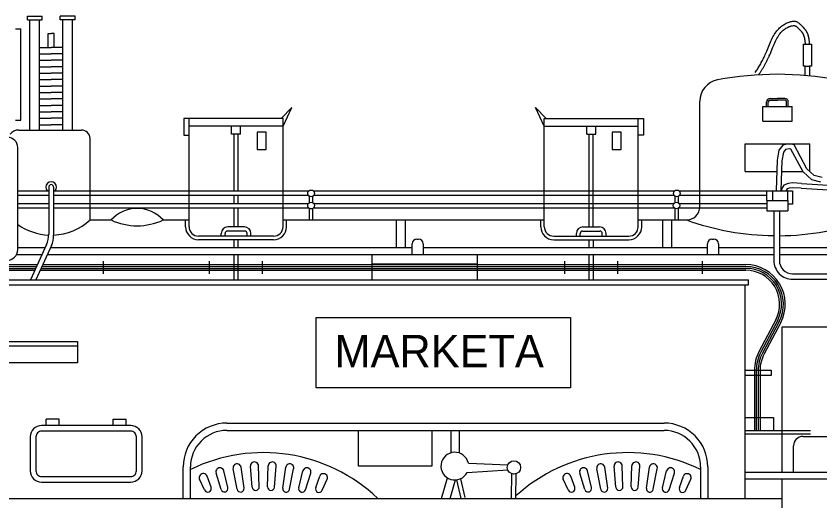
# Model space of a CAD drawing. Extents: x 2 to 10148, y 0 to 380.
# Drawn here: x 83.28 to 130.44, y 231.85 to 260.31 of the extents above; entities that cross this region are included whole.
import ezdxf

# ---------------------------------------------------------------- set-up
doc = ezdxf.new("R2010")
doc.units = 0

msp = doc.modelspace()

# ---------------------------------------------------------------- linework, layer by layer
for p, q in [((83.943, 260.309), (84.812, 260.309)), ((83.943, 260.081), (83.943, 260.309)), ((83.943, 260.081), (84.812, 260.081)), ((84.097, 253.621), (84.097, 260.081)), ((84.657, 253.621), (84.657, 260.081)), ((84.812, 260.081), (84.812, 260.309)), ((85.871, 260.081), (85.871, 260.309)), ((86.74, 260.309), (85.871, 260.309)), ((86.74, 260.081), (85.871, 260.081)), ((86.025, 253.621), (86.025, 260.081)), ((86.586, 253.621), (86.586, 260.081)), ((86.74, 260.081), (86.74, 260.309)), ((83.252, 259.551), (83.565, 259.551)), ((83.565, 254.191), (83.565, 259.551)), ((85.169, 258.469), (85.169, 259.279)), ((85.169, 259.279), (85.346, 259.279)), ((85.514, 259.279), (85.337, 259.279)), ((85.514, 258.469), (85.514, 259.279)), ((84.657, 258.469), (85.341, 258.469)), ((86.025, 258.469), (85.341, 258.469)), ((84.657, 258.091), (85.341, 258.091)), ((86.025, 258.091), (85.341, 258.091)), ((84.657, 257.713), (85.341, 257.713)), ((86.025, 257.713), (85.341, 257.713)), ((84.657, 257.335), (85.341, 257.335)), ((86.025, 257.335), (85.341, 257.335)), ((84.657, 256.957), (85.341, 256.957)), ((84.657, 256.579), (85.341, 256.579)), ((86.025, 256.957), (85.341, 256.957)), ((86.025, 256.579), (85.341, 256.579)), ((84.657, 256.201), (85.341, 256.201)), ((86.025, 256.201), (85.341, 256.201)), ((84.657, 255.824), (85.341, 255.824)), ((86.025, 255.824), (85.341, 255.824)), ((84.657, 255.446), (85.341, 255.446)), ((86.025, 255.446), (85.341, 255.446)), ((123.389, 249.124), (123.389, 255.308)), ((127.311, 255.002), (127.311, 255.266)), ((127.412, 255.002), (127.412, 255.282)), ((127.499, 255.369), (127.949, 255.369)), ((127.516, 255.47), (127.949, 255.47)), ((128.383, 255.47), (127.949, 255.47)), ((128.4, 255.369), (127.949, 255.369)), ((128.487, 255.002), (128.487, 255.282)), ((128.587, 255.002), (128.587, 255.266)), ((84.657, 255.068), (85.341, 255.068)), ((84.657, 254.69), (85.341, 254.69)), ((86.025, 255.068), (85.341, 255.068)), ((86.025, 254.69), (85.341, 254.69)), ((99.455, 254.94), (98.829, 254.295)), ((98.943, 253.85), (99.455, 254.94)), ((114.269, 253.85), (113.758, 254.94)), ((113.758, 254.94), (114.383, 254.295)), ((127.094, 254.147), (127.094, 255.002)), ((127.094, 255.002), (128.804, 255.002)), ((128.804, 254.147), (128.804, 255.002)), ((83.252, 254.191), (83.565, 254.191)), ((84.657, 254.312), (85.341, 254.312)), ((86.025, 254.312), (85.341, 254.312)), ((93.131, 254.297), (93.131, 253.327)), ((93.433, 254.295), (93.131, 254.297)), ((98.943, 254.295), (93.433, 254.295)), ((93.433, 247.943), (93.433, 254.295)), ((98.943, 247.943), (98.943, 254.295)), ((114.269, 247.943), (114.269, 254.295)), ((114.269, 254.295), (119.779, 254.295)), ((119.779, 254.295), (120.081, 254.297)), ((119.779, 247.943), (119.779, 254.295)), ((120.081, 254.297), (120.081, 253.327)), ((84.657, 253.934), (85.341, 253.934)), ((86.025, 253.934), (85.341, 253.934)), ((98.943, 253.85), (93.433, 253.85)), ((95.925, 253.375), (95.925, 253.85)), ((96.452, 253.375), (96.452, 253.85)), ((114.269, 253.85), (119.779, 253.85)), ((116.761, 253.375), (116.761, 253.85)), ((117.288, 253.375), (117.288, 253.85)), ((127.094, 254.147), (128.804, 254.147)), ((127.094, 254.147), (128.804, 254.147)), ((83.435, 253.621), (87.125, 253.621)), ((93.131, 253.327), (93.427, 253.327)), ((96.452, 253.375), (95.925, 253.375)), ((96.069, 250.05), (96.069, 253.375)), ((96.307, 250.05), (96.307, 253.375)), ((97.952, 253.487), (97.425, 253.487)), ((97.425, 253.487), (97.425, 252.477)), ((97.952, 252.477), (97.952, 253.487)), ((116.761, 253.375), (117.288, 253.375)), ((116.905, 247.938), (116.905, 253.375)), ((117.144, 247.938), (117.144, 253.375)), ((118.262, 253.487), (118.262, 252.477)), ((118.789, 253.487), (118.262, 253.487)), ((118.789, 252.477), (118.789, 253.487)), ((120.081, 253.327), (119.785, 253.327)), ((87.622, 248.34), (87.622, 253.124)), ((126.049, 252.805), (129.849, 252.805)), ((126.049, 251.19), (126.049, 252.805)), ((129.849, 251.19), (129.849, 252.805)), ((83.379, 246.6), (83.379, 252.597)), ((97.425, 252.477), (97.952, 252.477)), ((118.262, 252.477), (118.789, 252.477)), ((126.049, 251.19), (127.907, 251.19)), ((128.189, 251.19), (129.439, 251.19)), ((129.84, 251.19), (129.849, 251.19)), ((129.361, 250.486), (147.884, 249.35)), ((83.379, 250.05), (85.197, 250.05)), ((85.197, 250.271), (85.197, 247.504)), ((85.486, 250.271), (85.486, 247.444)), ((85.486, 250.05), (100.46, 250.05)), ((100.714, 250.05), (121.913, 250.05)), ((122.168, 250.05), (127.661, 250.05)), ((127.332, 249.478), (127.332, 250.056)), ((127.332, 250.056), (127.661, 250.056)), ((127.661, 250.056), (127.661, 249.481)), ((127.661, 250.056), (128.567, 250.056)), ((128.567, 249.478), (128.567, 250.056)), ((128.567, 250.056), (128.828, 250.056)), ((128.828, 250.056), (128.828, 249.271)), ((129.344, 250.205), (147.867, 249.069)), ((83.379, 249.799), (85.197, 249.799)), ((85.486, 249.799), (100.423, 249.799)), ((96.069, 249.301), (96.069, 249.799)), ((96.307, 249.301), (96.307, 249.799)), ((100.488, 249.351), (100.488, 249.735)), ((100.69, 249.349), (100.69, 249.738)), ((100.751, 249.799), (121.876, 249.799)), ((121.942, 249.351), (121.942, 249.735)), ((122.143, 249.349), (122.143, 249.738)), ((122.205, 249.799), (127.332, 249.799)), ((127.332, 249.478), (127.332, 248.872)), ((127.332, 249.478), (128.567, 249.478)), ((128.567, 249.478), (128.567, 248.872)), ((83.379, 249.301), (85.197, 249.301)), ((83.379, 249.05), (85.197, 249.05)), ((85.486, 249.301), (100.432, 249.301)), ((85.486, 249.05), (100.446, 249.05)), ((96.069, 247.938), (96.069, 249.05)), ((96.307, 247.938), (96.307, 249.05)), ((100.488, 248.34), (100.488, 249.016)), ((100.69, 248.34), (100.69, 249.019)), ((100.728, 249.05), (121.9, 249.05)), ((100.742, 249.301), (121.864, 249.301)), ((121.942, 248.34), (121.942, 249.016)), ((122.143, 248.34), (122.143, 249.019)), ((122.156, 249.05), (127.332, 249.05)), ((122.192, 249.301), (127.332, 249.301)), ((128.828, 249.271), (128.57, 249.271)), ((127.332, 248.872), (128.567, 248.872)), ((127.735, 248.872), (127.735, 245.966)), ((128.063, 248.872), (128.063, 245.966)), ((87.622, 248.34), (88.858, 248.34)), ((91.91, 248.34), (93.433, 248.34)), ((93.226, 247.943), (93.226, 248.34)), ((98.943, 248.34), (114.269, 248.34)), ((99.15, 247.943), (99.15, 248.34)), ((105.593, 246.725), (105.593, 248.34)), ((106.124, 246.725), (106.124, 248.34)), ((114.063, 247.943), (114.063, 248.34)), ((119.779, 248.34), (122.606, 248.34)), ((119.986, 247.943), (119.986, 248.34)), ((121.217, 246.725), (121.217, 248.34)), ((121.748, 246.725), (121.748, 248.34)), ((96.691, 247.692), (95.685, 247.692)), ((96.676, 247.938), (95.701, 247.938)), ((116.521, 247.692), (117.528, 247.692)), ((116.537, 247.938), (117.512, 247.938)), ((98.39, 247.39), (93.986, 247.39)), ((98.39, 247.183), (93.986, 247.183)), ((95.315, 247.39), (95.315, 247.553)), ((95.542, 247.39), (95.542, 247.549)), ((96.069, 246.725), (96.069, 247.183)), ((96.307, 246.725), (96.307, 247.183)), ((96.834, 247.39), (96.834, 247.549)), ((97.061, 247.39), (97.061, 247.553)), ((106.791, 247.218), (106.899, 247.218)), ((114.822, 247.39), (119.226, 247.39)), ((114.822, 247.183), (119.226, 247.183)), ((116.152, 247.39), (116.152, 247.553)), ((116.378, 247.39), (116.378, 247.549)), ((116.909, 246.725), (116.909, 247.183)), ((117.148, 246.725), (117.148, 247.183)), ((117.671, 247.39), (117.671, 247.549)), ((117.897, 247.39), (117.897, 247.553)), ((124.108, 247.218), (124.215, 247.218)), ((83.379, 246.725), (84.988, 246.725)), ((85.067, 246.899), (84.131, 244.825)), ((85.356, 246.839), (84.447, 244.825)), ((85.304, 246.725), (106.52, 246.725)), ((106.52, 246.315), (106.52, 246.947)), ((107.17, 246.947), (107.17, 246.323)), ((107.17, 246.725), (123.836, 246.725)), ((123.836, 246.315), (123.836, 246.947)), ((124.487, 246.947), (124.487, 246.323)), ((124.487, 246.725), (127.735, 246.725)), ((128.063, 246.725), (149.521, 246.725)), ((83.311, 246.315), (84.803, 246.315)), ((85.119, 246.315), (127.735, 246.315)), ((96.069, 244.825), (96.069, 246.315)), ((96.307, 244.825), (96.307, 246.315)), ((104.168, 244.825), (104.168, 246.315)), ((110.343, 244.825), (110.343, 246.315)), ((116.909, 244.825), (116.909, 246.315)), ((117.148, 244.825), (117.148, 246.315)), ((128.063, 246.315), (151.309, 246.315)), ((82.112, 245.722), (84.536, 245.722)), ((84.852, 245.722), (126.088, 245.722)), ((88.406, 245.189), (88.406, 245.923)), ((94.631, 245.189), (94.631, 245.923)), ((97.745, 245.189), (97.745, 245.923)), ((104.168, 245.766), (110.343, 245.766)), ((115.472, 245.189), (115.472, 245.923)), ((118.586, 245.189), (118.586, 245.923)), ((123.548, 245.189), (123.548, 245.923)), ((125.641, 245.722), (126.088, 245.722)), ((82.112, 245.612), (84.486, 245.612)), ((82.112, 245.501), (84.436, 245.501)), ((82.112, 245.39), (84.386, 245.39)), ((84.702, 245.39), (126.088, 245.39)), ((84.752, 245.501), (126.088, 245.501)), ((84.802, 245.612), (126.088, 245.612)), ((125.641, 245.612), (126.088, 245.612)), ((125.641, 245.501), (126.088, 245.501)), ((125.641, 245.39), (126.088, 245.39)), ((82.112, 244.825), (126.241, 244.825)), ((126.241, 244.54), (126.241, 244.825)), ((128.841, 245.189), (137.963, 245.189)), ((128.841, 244.86), (137.963, 244.86)), ((62.352, 244.54), (126.241, 244.54)), ((126.049, 232), (126.049, 244.54)), ((100.892, 238.49), (100.892, 242.618)), ((100.892, 242.618), (115.816, 242.618)), ((115.816, 242.618), (115.816, 238.49)), ((127.847, 242.476), (126.878, 240.635)), ((127.945, 242.424), (126.976, 240.584)), ((128.043, 242.373), (127.074, 240.532)), ((128.141, 242.321), (127.172, 240.481)), ((128.234, 242.07), (139.894, 242.07)), ((128.234, 233.538), (128.234, 242.07)), ((82.88, 241.215), (86.894, 241.215)), ((86.894, 241.215), (86.894, 239.958)), ((82.88, 240.944), (86.894, 240.944)), ((86.894, 239.958), (82.88, 239.958)), ((126.049, 239.527), (127.581, 239.527)), ((127.581, 239.214), (126.082, 239.214)), ((126.597, 239.497), (126.597, 235.97)), ((126.707, 239.497), (126.707, 235.97)), ((126.818, 239.497), (126.818, 235.97)), ((126.928, 239.497), (126.928, 235.97)), ((127.581, 239.527), (127.581, 239.214)), ((115.816, 238.49), (100.892, 238.49)), ((126.049, 236.753), (127.711, 236.753)), ((127.711, 236.753), (127.711, 235.97)), ((90.006, 236.275), (84.778, 236.275)), ((85.048, 236.275), (85.048, 236.645)), ((85.804, 236.645), (85.048, 236.645)), ((85.804, 236.275), (85.804, 236.645)), ((88.98, 236.645), (89.736, 236.645)), ((88.98, 236.275), (88.98, 236.645)), ((89.736, 236.275), (89.736, 236.645)), ((95.649, 236.417), (121.3, 236.417)), ((90.006, 235.943), (84.778, 235.943)), ((95.649, 235.99), (121.3, 235.99)), ((103.363, 233.892), (103.363, 235.993)), ((107.677, 235.993), (107.677, 233.892)), ((108.803, 234.694), (108.803, 235.993)), ((109.303, 234.694), (109.303, 235.993)), ((129.897, 235.97), (126.049, 235.97)), ((84.115, 235.611), (84.115, 233.614)), ((84.446, 235.611), (84.446, 233.614)), ((90.338, 233.614), (90.338, 235.611)), ((90.67, 233.614), (90.67, 235.611)), ((129.897, 235.759), (126.049, 235.759)), ((129.446, 235.637), (134.516, 235.637)), ((128.894, 233.538), (128.894, 235.084)), ((97.547, 232.683), (97.51, 233.911)), ((98.033, 232.682), (98.07, 233.911)), ((109.816, 234.072), (112.125, 233.961)), ((118.882, 232.683), (118.845, 233.911)), ((119.367, 232.682), (119.405, 233.911)), ((93.085, 232), (93.085, 233.853)), ((93.512, 232), (93.512, 233.853)), ((95.306, 232.522), (95.013, 233.488)), ((95.701, 232.635), (95.468, 233.619)), ((96.251, 232.537), (96.014, 233.743)), ((96.655, 232.606), (96.481, 233.823)), ((97.138, 232.66), (97.038, 233.885)), ((98.442, 232.659), (98.543, 233.885)), ((98.925, 232.605), (99.1, 233.822)), ((99.329, 232.536), (99.566, 233.742)), ((99.865, 232.62), (100.112, 233.617)), ((100.259, 232.506), (100.567, 233.486)), ((107.677, 233.892), (103.363, 233.892)), ((109.748, 233.523), (112.124, 233.676)), ((112.353, 232), (112.367, 233.473)), ((112.603, 232), (112.617, 233.47)), ((116.641, 232.522), (116.348, 233.488)), ((117.035, 232.635), (116.802, 233.619)), ((117.585, 232.537), (117.349, 233.743)), ((117.99, 232.606), (117.815, 233.823)), ((118.472, 232.66), (118.372, 233.885)), ((119.777, 232.659), (119.878, 233.885)), ((120.259, 232.605), (120.434, 233.822)), ((120.664, 232.536), (120.901, 233.742)), ((121.2, 232.62), (121.447, 233.617)), ((121.594, 232.506), (121.902, 233.486)), ((123.437, 233.853), (123.437, 232)), ((123.864, 233.853), (123.864, 232)), ((126.049, 233.538), (136.63, 233.538)), ((84.778, 233.282), (90.006, 233.282)), ((94.343, 232.495), (94.047, 233.122)), ((94.722, 232.652), (94.484, 233.303)), ((100.859, 232.63), (101.096, 233.301)), ((101.238, 232.473), (101.533, 233.12)), ((108.24, 232), (108.584, 233.205)), ((108.741, 231.984), (109.053, 233.091)), ((109.112, 233.083), (109.366, 232)), ((109.356, 233.14), (109.609, 232.057)), ((115.678, 232.495), (115.381, 233.122)), ((116.057, 232.652), (115.819, 233.303)), ((122.194, 232.63), (122.431, 233.301)), ((122.573, 232.473), (122.868, 233.12)), ((126.049, 233.14), (136.63, 233.14)), ((128.234, 220.79), (128.234, 233.14)), ((84.778, 232.95), (90.006, 232.95)), ((68.717, 232), (128.234, 232))]:
    msp.add_line(p, q)
for points in [[(129.574, 257.373), (129.478, 257.373), (129.478, 258.651), (129.954, 258.651), (129.954, 257.373), (129.835, 257.373)], [(129.574, 256.831), (129.574, 257.373), (129.835, 257.373), (129.835, 256.822)], [(130.566, 250.826), (130.102, 250.95), (129.68, 251.337), (128.921, 252.753), (128.626, 252.803), (128.268, 252.726), (128.036, 252.443), (127.93, 251.851), (127.867, 250.075)], [(130.493, 250.554), (129.962, 250.696), (129.454, 251.161), (128.738, 252.498), (128.632, 252.517), (128.423, 252.472), (128.3, 252.322), (128.211, 251.821), (128.149, 250.065)], [(129.361, 250.486), (128.838, 250.516), (128.579, 250.481), (128.316, 250.39), (128.225, 250.22), (128.176, 250.059)], [(129.345, 250.205), (128.849, 250.233), (128.644, 250.206), (128.512, 250.16), (128.486, 250.111), (128.469, 250.056)]]:
    msp.add_lwpolyline(points)
for centre, radius in [((100.587, 249.903), 0.195), ((122.041, 249.903), 0.195), ((100.587, 249.184), 0.195), ((122.028, 249.196), 0.195), ((112.49, 233.817), 0.392)]:
    msp.add_circle(centre, radius)
for centre, radius, start, end in [((124.666, 255.308), 1.277, 100.6248, 180), ((127.949, 237.807), 19.083, 79.3752, 100.6248), ((127.516, 255.266), 0.204, 90, 180), ((127.499, 255.282), 0.0867, 90, 180), ((128.383, 255.266), 0.204, 0, 90), ((128.4, 255.282), 0.0867, 0, 90), ((83.435, 252.985), 0.636, 90, 142.2355), ((87.125, 253.124), 0.497, 0, 90), ((82.79, 252.597), 0.589, 0, 90), ((85.341, 250.271), 0.316, 315.6951, 224.3049), ((85.341, 250.271), 0.145, 0, 180), ((90.384, 246.975), 2.048, 41.8081, 138.1919), ((122.606, 249.124), 0.784, 270, 0), ((85.341, 250.833), 3.379, 234.4988, 267.5359), ((85.341, 250.833), 3.379, 272.4513, 312.4487), ((90.384, 251.589), 3.589, 244.8327, 295.1673), ((127.949, 263.379), 15.96, 250.4387, 269.2306), ((127.949, 263.379), 15.96, 270.4097, 289.5613), ((93.986, 247.943), 0.76, 180, 270), ((93.986, 247.943), 0.553, 180, 270), ((95.701, 247.553), 0.385, 90, 180), ((95.685, 247.549), 0.143, 90, 180), ((96.676, 247.553), 0.385, 0, 90), ((96.691, 247.549), 0.143, 0, 90), ((98.39, 247.943), 0.76, 270, 0), ((98.39, 247.943), 0.553, 270, 0), ((114.822, 247.943), 0.76, 180, 270), ((114.822, 247.943), 0.553, 180, 270), ((116.537, 247.553), 0.385, 90, 180), ((116.521, 247.549), 0.143, 90, 180), ((117.512, 247.553), 0.385, 0, 90), ((117.528, 247.549), 0.143, 0, 90), ((119.226, 247.943), 0.553, 270, 0), ((119.226, 247.943), 0.76, 270, 0), ((83.725, 247.504), 1.471, 335.7239, 0), ((84.014, 247.444), 1.471, 335.7239, 0), ((106.791, 246.947), 0.271, 90, 180), ((106.899, 246.947), 0.271, 0, 90), ((124.108, 246.947), 0.271, 90, 180), ((124.215, 246.947), 0.271, 0, 90), ((82.745, 246.6), 0.634, 270, 0), ((126.088, 243.402), 2.32, 332.2295, 90.0039), ((128.841, 245.966), 1.106, 180.0045, 270.0045), ((128.841, 245.966), 0.778, 180.0227, 270.0228), ((126.088, 243.402), 2.209, 332.2279, 90.0023), ((126.088, 243.402), 2.099, 332.2261, 90.0005), ((126.088, 243.402), 1.988, 332.2242, 89.9986), ((129.039, 239.498), 2.442, 152.243, 180.0172), ((129.039, 239.497), 2.332, 152.2068, 179.9811), ((129.039, 239.497), 2.221, 152.2193, 179.9936), ((129.039, 239.496), 2.111, 152.1782, 179.9525), ((84.778, 235.612), 0.663, 90.0273, 180.0273), ((90.006, 235.611), 0.664, 0.0158, 90.0159), ((95.649, 233.853), 2.564, 90.0003, 180.0004), ((121.3, 233.853), 2.564, 359.9996, 89.9997), ((84.778, 235.611), 0.332, 89.9841, 179.9842), ((90.006, 235.611), 0.332, 0.0158, 90.0159), ((95.649, 233.853), 2.137, 89.9959, 179.9959), ((121.3, 233.853), 2.137, 0.0041, 90.0041), ((129.446, 235.084), 0.552, 90, 180), ((97.787, 224.951), 9.733, 46.4042, 116.054), ((109.022, 233.892), 0.815, 12.7647, 333.0293), ((119.162, 224.951), 9.733, 63.9461, 132.3541), ((96.247, 233.786), 0.237, 8.887, 190.3588), ((97.274, 233.901), 0.237, 2.4584, 183.9302), ((98.307, 233.901), 0.237, 356.0298, 177.5017), ((99.334, 233.785), 0.237, 349.6012, 171.0731), ((117.582, 233.786), 0.237, 8.887, 190.3588), ((118.608, 233.901), 0.237, 2.4584, 183.9302), ((119.641, 233.901), 0.237, 356.0298, 177.5017), ((120.668, 233.785), 0.237, 349.6012, 171.0731), ((84.778, 233.613), 0.663, 179.9727, 269.9727), ((84.778, 233.614), 0.332, 180.0158, 270.0159), ((90.006, 233.614), 0.664, 269.9841, 359.9842), ((90.006, 233.614), 0.332, 269.9841, 359.9842), ((94.264, 233.216), 0.237, 21.7441, 203.2159), ((95.239, 233.556), 0.237, 15.3155, 196.7874), ((100.341, 233.555), 0.237, 343.1727, 164.6445), ((101.316, 233.213), 0.237, 336.7441, 158.2159), ((115.599, 233.216), 0.237, 21.7441, 203.2159), ((116.574, 233.556), 0.237, 15.3155, 196.7874), ((121.675, 233.555), 0.237, 343.1727, 164.6445), ((122.651, 233.213), 0.237, 336.7441, 158.2159), ((94.531, 232.576), 0.205, 203.2159, 21.7441), ((95.503, 232.581), 0.205, 196.7874, 15.3155), ((96.452, 232.574), 0.205, 190.3588, 8.887), ((97.342, 232.674), 0.205, 183.9302, 2.4584), ((98.237, 232.673), 0.205, 177.5017, 356.0298), ((99.127, 232.573), 0.205, 171.0731, 349.6012), ((100.063, 232.565), 0.205, 164.6445, 343.1727), ((101.05, 232.554), 0.205, 158.2159, 336.7441), ((115.866, 232.576), 0.205, 203.2159, 21.7441), ((116.837, 232.581), 0.205, 196.7874, 15.3155), ((117.787, 232.574), 0.205, 190.3588, 8.887), ((118.677, 232.674), 0.205, 183.9302, 2.4584), ((119.572, 232.673), 0.205, 177.5017, 356.0298), ((120.462, 232.573), 0.205, 171.0731, 349.6012), ((121.397, 232.565), 0.205, 164.6445, 343.1727), ((122.384, 232.554), 0.205, 158.2159, 336.7441)]:
    msp.add_arc(centre, radius, start, end)
for points in [[(126.642, 257), (127.097, 257.634), (127.807, 259.517), (128.909, 260.135), (129.417, 259.722), (129.789, 259.232), (129.816, 258.663)], [(126.839, 256.858), (127.314, 257.518), (128.004, 259.348), (128.883, 259.842), (129.241, 259.551), (129.549, 259.145), (129.573, 258.651)]]:
    msp.add_open_spline(points, degree=2)

# ---------------------------------------------------------------- texts
msp.add_text('MARKETA', height=1.9).set_placement((101.962, 239.697))

doc.saveas('drawing.dxf')
